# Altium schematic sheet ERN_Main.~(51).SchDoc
size A; SheetNumber: 1; SheetTotal: 2; SPICEModelCacheDBTNACQE: <root> / <DocumentId>DBTNACQE</DocumentId> / <CacheFrame Number="0"> / <Model Name="irf1010" Kind="CKT"> / <Text>*IRF1010 MCE 4-2-96 / *55V  75A .014 ohm HEXFET pkg:TO-220 2,1,3 / .SUBCKT IRF1010  10 20 40 40 / M1   1  2  3  3  DMOS L=1U W=1U / RD  10  1  5.65M / RS  30  3  1.35M / RG  20  2  12.1 / CGS  2  3  2.15N / EGD 12  0  2  1  1 / VFB 14  0  0 / FFB  2  1  VFB  1 / CGD 13 14  4.49N / R1  13  0  1 / D1  12 13  DLIM / DDG 15 14  DCGD / R2  12 15  1 / D2  15  0  DLIM / DSD  3 10  DSUB / LS  30 40  7.5N / .MODEL DMOS NMOS (LEVEL=3 THETA=60M VMAX=114K ETA=2M VTO=3 KP=19.4) / .MODEL DCGD D (CJO=4.49N VJ=.6 M=.68) / .MODEL DSUB D (IS=311N N=1.5 RS=8.67M BV=55 CJO=4.08N VJ=.8 M=.42 TT=100N) / .MODEL DLIM D (IS=100U) / .ENDS IRF1010</Text> / </Model> / </CacheFrame> / </root>
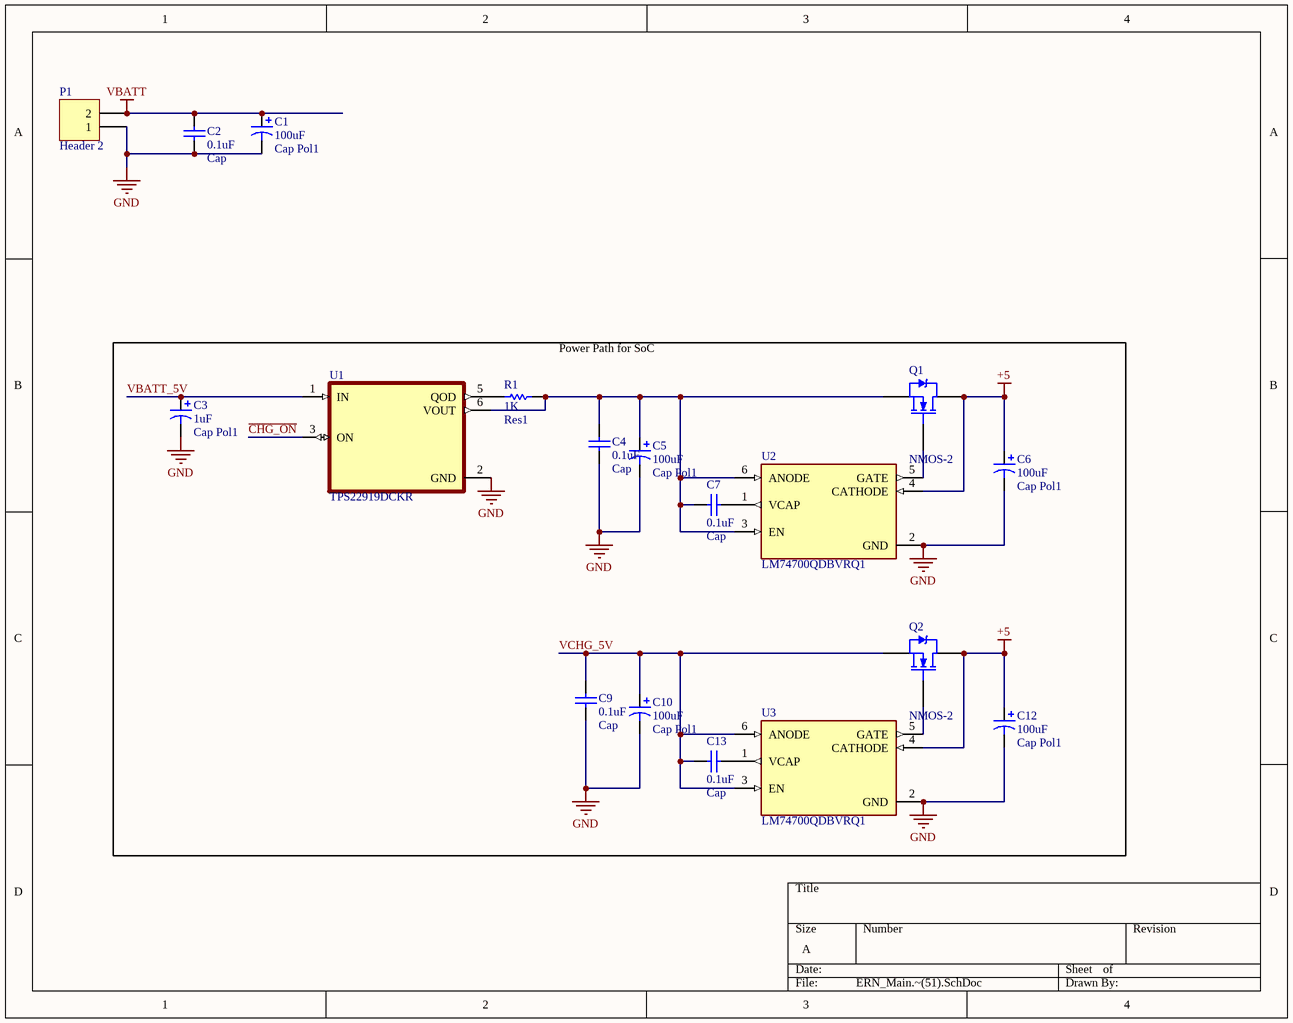
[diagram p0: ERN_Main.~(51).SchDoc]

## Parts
C1  Cap Pol1  value 100uF  [RB7.6-15]
C2  Cap  value 0.1uF  [RAD-0.3]
C3  Cap Pol1  value 1uF  [RB7.6-15]
C4  Cap  value 0.1uF  [RAD-0.3]
C5  Cap Pol1  value 100uF  [RB7.6-15]
C6  Cap Pol1  value 100uF  [RB7.6-15]
C7  Cap  value 0.1uF  [RAD-0.3]
C9  Cap  value 0.1uF  [RAD-0.3]
C10  Cap Pol1  value 100uF  [RB7.6-15]
C12  Cap Pol1  value 100uF  [RB7.6-15]
C13  Cap  value 0.1uF  [RAD-0.3]
P1  Header 2  [HDR1X2]
Q1  NMOS-2  [TO-220AB]
Q2  NMOS-2  [TO-220AB]
R1  Res1  value 1K  [AXIAL-0.3]
U1  TPS22919DCKR  [SOT65P210X110-6N]
U2  LM74700QDBVRQ1  [SOT95P280X145-6N]
U3  LM74700QDBVRQ1  [SOT95P280X145-6N]

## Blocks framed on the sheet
Power Path for SoC: C3-C7 C9 C10 C12 C13 Q1 Q2 R1 U1-U3

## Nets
+5: C6.1 C12.1 Q1.2(D) Q2.2(D) U2.4(CATHODE) U3.4(CATHODE)
GND: C1.2 C2.1 C3.2 C4.1 C5.2 C6.2 C9.1 C10.2 C12.2 P1.1 U1.2(GND) U2.2(GND) U3.2(GND)
VBATT: C1.1 C2.2 P1.2
~{CHG_ON}: U1.3(ON)
VBATT_5V: C3.1 U1.1(IN)
VCHG_5V: C9.2 C10.1 C13.2 Q2.3(S) U3.3(EN) U3.6(ANODE)
NetC4_2: C4.2 C5.1 C7.2 Q1.3(S) R1.1 U1.6(VOUT) U2.3(EN) U2.6(ANODE)
NetC7_1: C7.1 U2.1(VCAP)
NetC13_1: C13.1 U3.1(VCAP)
NetQ1_1: Q1.1(G) U2.5(GATE)
NetQ2_1: Q2.1(G) U3.5(GATE)
NetR1_2: R1.2 U1.5(QOD)

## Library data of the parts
C1 C3 C5 C6 C10 C12 = Cap Pol1: Polarized Capacitor (Radial)
C2 C4 C7 C9 C13 = Cap: Capacitor
P1 = Header 2: Header, 2-Pin
Q1 Q2 = NMOS-2: N-Channel Power MOSFET; Note: Pin 2 is electrically connected to pin 4.
R1 = Res1: Resistor
U1 = TPS22919DCKR: 5.5-V, 1.5-A, 90-mÎ© load switch with adj. output discharge; MF: Texas Instruments
U2 U3 = LM74700QDBVRQ1: 3.2-V to 65-V, 80-uA IQ automotive ideal diode controller; MF: Texas Instruments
